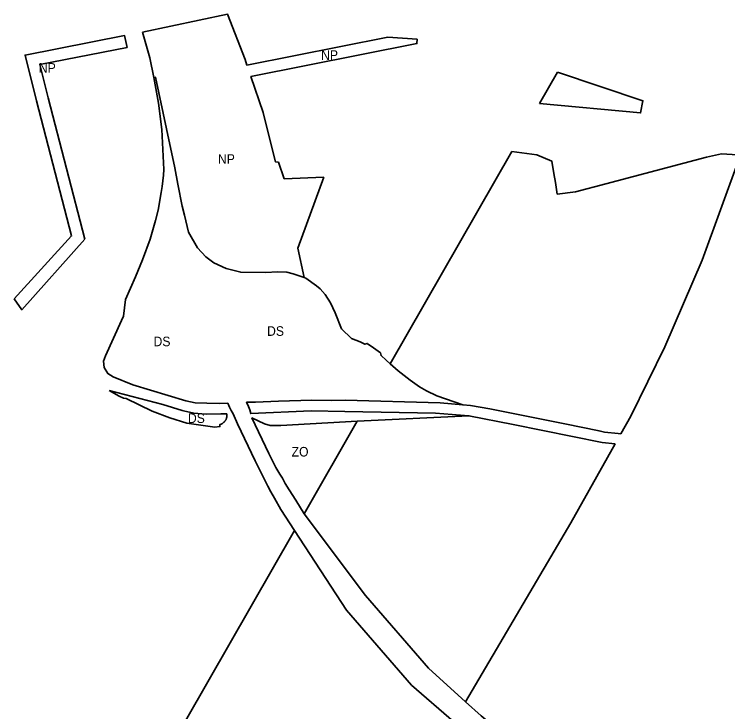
# Model space of a CAD drawing. Extents: x -650971 to -642489, y -1074311 to -1062745.
# Drawn here: x -647969 to -647077, y -1068126 to -1067254 of the extents above; entities that cross this region are included whole.
import ezdxf

# ---------------------------------------------------------------- set-up
doc = ezdxf.new("R2010")
doc.units = 0
doc.header["$LTSCALE"] = 4.8
for name, color, linetype, lineweight in [('24', 7, 'Continuous', 35), ('25', 7, 'Continuous', 35), ('42', 7, 'Continuous', 35), ('48', 7, 'Continuous', 35), ('62', 7, 'Continuous', 35)]:
    doc.layers.add(name, color=color, linetype=linetype, lineweight=lineweight)

msp = doc.modelspace()

# ---------------------------------------------------------------- linework, layer by layer
at = {"layer": '24'}
for points in [[(-647695.71, -1067753.9), (-647697.85, -1067749.46), (-647699.89, -1067745.24), (-647702.21, -1067740.43), (-647713.15, -1067741), (-647728.29, -1067740.64), (-647743.12, -1067739.93), (-647754.88, -1067737.59), (-647821.02, -1067717.33), (-647845.74, -1067707.59), (-647852.3, -1067703.36), (-647856.9, -1067695.97), (-647857.51, -1067687.74), (-647855.24, -1067681.26), (-647835.06, -1067637.01), (-647832.8, -1067631.53), (-647829.97, -1067610.62), (-647817.59, -1067582.4), (-647808.71, -1067561.03), (-647799.39, -1067535.48), (-647792.54, -1067511.85), (-647789.39, -1067498.84), (-647785.64, -1067477.02), (-647784.36, -1067469.6), (-647782.5, -1067455.11), (-647782.39, -1067448.34), (-647784.55, -1067398.01), (-647788.77, -1067365.03), (-647794.54, -1067333.14)], [(-647794.54, -1067333.14), (-647792.52, -1067332.74), (-647778.78, -1067397.1), (-647768.5, -1067446.04), (-647764.89, -1067466.64), (-647759.16, -1067494.01), (-647756.55, -1067505.32), (-647751.41, -1067526.58), (-647740.124, -1067546.265), (-647729.802, -1067557.462), (-647719.661, -1067564.884), (-647704.458, -1067572.034), (-647685.968, -1067576.68), (-647654.743, -1067576.996), (-647640.087, -1067576.306), (-647628.441, -1067576.759), (-647620.586, -1067578.478), (-647606.559, -1067583.309)], [(-647606.559, -1067583.309), (-647604.415, -1067584.047), (-647591.227, -1067593.613), (-647586.864, -1067597.411), (-647580.539, -1067604.432), (-647573.605, -1067614.951), (-647567.744, -1067627.24), (-647560.187, -1067647.458), (-647547.663, -1067659.519), (-647536.83, -1067663.64), (-647530.82, -1067666.65), (-647527.76, -1067665.65), (-647520.13, -1067671.13), (-647511.24, -1067677.53), (-647510.6, -1067680.86), (-647503.97, -1067686.73), (-647499.095, -1067691.163)], [(-647499.095, -1067691.163), (-647489.3, -1067700.07), (-647474.13, -1067711.81), (-647462.45, -1067719.84), (-647453.87, -1067724.97), (-647440.81, -1067731.38), (-647408.2, -1067742.37)], [(-647850.45, -1067724.77), (-647783.54, -1067742.11), (-647759.13, -1067749.54), (-647757.74, -1067749.96), (-647744.74, -1067752.93), (-647734.69, -1067753.66), (-647728.98, -1067754.07), (-647711.09, -1067753.71), (-647703.4, -1067753.8)], [(-647703.4, -1067753.8), (-647703.34, -1067754.304), (-647703.3, -1067754.818), (-647703.282, -1067755.341), (-647703.287, -1067755.87), (-647703.315, -1067756.406), (-647703.368, -1067756.946), (-647703.445, -1067757.489), (-647703.547, -1067758.033), (-647703.675, -1067758.576), (-647703.83, -1067759.117), (-647704.01, -1067759.653), (-647704.216, -1067760.184), (-647704.447, -1067760.707), (-647704.704, -1067761.22), (-647704.985, -1067761.721), (-647705.29, -1067762.21), (-647705.617, -1067762.683), (-647705.966, -1067763.14), (-647706.335, -1067763.579), (-647706.723, -1067763.999), (-647707.128, -1067764.398), (-647707.55, -1067764.777), (-647707.985, -1067765.133), (-647708.433, -1067765.466), (-647708.892, -1067765.776), (-647709.359, -1067766.062), (-647709.834, -1067766.324), (-647710.315, -1067766.562), (-647710.799, -1067766.777), (-647711.286, -1067766.968), (-647711.773, -1067767.135), (-647712.26, -1067767.28), (-647712.01, -1067769.63), (-647718.54, -1067770.6), (-647753.53, -1067765.58), (-647774.54, -1067758.68), (-647796.87, -1067750.25), (-647829.49, -1067734.58), (-647832.56, -1067734.22), (-647838.18, -1067731.62), (-647850.45, -1067724.77)], [(-647408.2, -1067742.37), (-647436.72, -1067740.02), (-647555.58, -1067736.71), (-647572.33, -1067737.03), (-647596.91, -1067736.61), (-647638.75, -1067738.03), (-647667.76, -1067739.01), (-647678.66, -1067739.38), (-647676.47, -1067744.5), (-647674.67, -1067748.73), (-647673.47, -1067753.48), (-647597.83, -1067750.21), (-647555.67, -1067750.91), (-647442.6, -1067753.13), (-647400.63, -1067756.19), (-647540.208, -1067762.876)], [(-647618.773, -1067899.914), (-647635.77, -1067873.43), (-647643.83, -1067859.13), (-647648.33, -1067851.17), (-647651.94, -1067844.36), (-647668.13, -1067812.76), (-647690.19, -1067766.37), (-647695.71, -1067753.9)], [(-647540.208, -1067762.876), (-647635.758, -1067768.38), (-647649.22, -1067768.38), (-647656.469, -1067766.309), (-647672.05, -1067758.98), (-647650.8, -1067803.28), (-647642.29, -1067820.76), (-647637.21, -1067829.29), (-647633.69, -1067834.31), (-647630.3, -1067841.02), (-647625.37, -1067848.86), (-647617.25, -1067861.95), (-647606.818, -1067879.061)], [(-647606.818, -1067879.061), (-647530.038, -1067980.839), (-647451.024, -1068071.886), (-647405.026, -1068113.904)], [(-647419.74, -1068138.917), (-647419.713, -1068138.871), (-647472.338, -1068093.096), (-647553.628, -1067999.427), (-647618.773, -1067899.914)], [(-647405.026, -1068113.904), (-647385.13, -1068131.51), (-647353.81, -1068157.67), (-647350.6, -1068160.26), (-647349.59, -1068163.24), (-647347.74, -1068162.54), (-647295.47, -1068201.09), (-647246.8, -1068233.08), (-647243.39, -1068235.26), (-647186.26, -1068269.45), (-647142.41, -1068293.81), (-647099.2, -1068318.27), (-647053.75, -1068342.11)]]:
    msp.add_lwpolyline(points, dxfattribs=at)
at = {"layer": '25'}
for p, q in [((-647312.383, -1067365.484), (-647289.924, -1067326.309)), ((-647499.095, -1067691.163), (-647346.944, -1067425.768))]:
    msp.add_line(p, q, dxfattribs=at)
for points in [[(-647289.924, -1067326.309), (-647183.09, -1067362.16), (-647185.93, -1067377.38), (-647312.383, -1067365.484)], [(-647346.944, -1067425.768), (-647315.89, -1067429.71), (-647296.75, -1067437.91), (-647294.31, -1067453.26), (-647292.51, -1067464.56), (-647290.23, -1067478.89), (-647267.49, -1067476.23), (-647252.99, -1067472.35), (-647243.39, -1067469.81), (-647103.55, -1067432.54), (-647084.77, -1067428.64), (-647064.87, -1067429.73), (-647061.252, -1067430.908)], [(-647061.252, -1067430.908), (-647108.971, -1067561.55), (-647155.592, -1067670.17), (-647198.088, -1067756.5), (-647210.537, -1067778.594)], [(-647408.2, -1067742.37), (-647440.81, -1067731.38), (-647453.87, -1067724.97), (-647462.45, -1067719.84), (-647474.13, -1067711.81), (-647489.3, -1067700.07), (-647499.095, -1067691.163)], [(-647210.537, -1067778.594), (-647213.92, -1067778.26), (-647231.17, -1067776.55), (-647237.91, -1067775.18), (-647280.78, -1067766.44), (-647374.55, -1067747.34), (-647398.74, -1067743.15), (-647408.2, -1067742.37)], [(-647606.818, -1067879.061), (-647540.208, -1067762.876), (-647400.63, -1067756.19)], [(-647400.63, -1067756.19), (-647345.11, -1067767.28), (-647233.83, -1067789.69), (-647217.611, -1067791.149)], [(-647217.611, -1067791.149), (-647273.297, -1067889.981), (-647405.026, -1068113.904)], [(-647405.026, -1068113.904), (-647451.024, -1068071.886), (-647530.038, -1067980.839), (-647606.818, -1067879.061)], [(-647791.055, -1068200.507), (-647781.346, -1068183.485), (-647618.773, -1067899.914)], [(-647618.773, -1067899.914), (-647553.628, -1067999.427), (-647472.338, -1068093.096), (-647419.713, -1068138.871), (-647419.74, -1068138.917)]]:
    msp.add_lwpolyline(points, dxfattribs=at)
at = {"layer": '42'}
msp.add_lwpolyline([(-647606.818, -1067879.061), (-647617.25, -1067861.95), (-647625.37, -1067848.86), (-647630.3, -1067841.02), (-647633.69, -1067834.31), (-647637.21, -1067829.29), (-647642.29, -1067820.76), (-647650.8, -1067803.28), (-647672.05, -1067758.98), (-647656.469, -1067766.309), (-647649.22, -1067768.38), (-647635.758, -1067768.38), (-647540.208, -1067762.876)], close=True, dxfattribs=at)
at = {"layer": '48'}
for points in [[(-647809.02, -1067276.271), (-647702.42, -1067253.98), (-647680.64, -1067310.37), (-647678.21, -1067317.562), (-647501.968, -1067282.642), (-647465.203, -1067285.115)], [(-647794.54, -1067333.14), (-647799.76, -1067308.3), (-647809.02, -1067276.271)], [(-647969.29, -1067609.79), (-647897.637, -1067531.223), (-647941.289, -1067362.104), (-647955.805, -1067305.106), (-647831.28, -1067280.69), (-647828.104, -1067295.352)], [(-647465.203, -1067285.115), (-647465.699, -1067290.747), (-647673.367, -1067331.895), (-647658.13, -1067376.99), (-647645.78, -1067425.81), (-647642.686, -1067438.46), (-647638.68, -1067439.06)], [(-647828.104, -1067295.352), (-647937.355, -1067316.774), (-647926.759, -1067358.379), (-647881.085, -1067535.333), (-647959.832, -1067623.65), (-647969.29, -1067609.79)], [(-647606.559, -1067583.309), (-647620.586, -1067578.478), (-647628.441, -1067576.759), (-647640.087, -1067576.306), (-647654.743, -1067576.996), (-647685.968, -1067576.68), (-647704.458, -1067572.034), (-647719.661, -1067564.884), (-647729.802, -1067557.462), (-647740.124, -1067546.265), (-647751.41, -1067526.58), (-647756.55, -1067505.32), (-647759.16, -1067494.01), (-647764.89, -1067466.64), (-647768.5, -1067446.04), (-647778.78, -1067397.1), (-647792.52, -1067332.74), (-647794.54, -1067333.14)], [(-647638.68, -1067439.06), (-647631.59, -1067459.72), (-647582.2, -1067457.65)], [(-647582.2, -1067457.65), (-647614.75, -1067546.53), (-647606.559, -1067583.309)]]:
    msp.add_lwpolyline(points, dxfattribs=at)

# ---------------------------------------------------------------- texts
at = {"layer": '62', "width": 0.95}
for s, p in [('NP', (-647585.583, -1067311.041)), ('NP', (-647938.583, -1067327.041)), ('NP', (-647714.583, -1067441.041)), ('DS', (-647653.118, -1067656.225)), ('DS', (-647795.118, -1067669.225)), ('DS', (-647752.118, -1067765.225)), ('ZO', (-647622.423, -1067807.188))]:
    msp.add_text(s, height=12, dxfattribs=at).set_placement(p)

doc.saveas('drawing.dxf')
